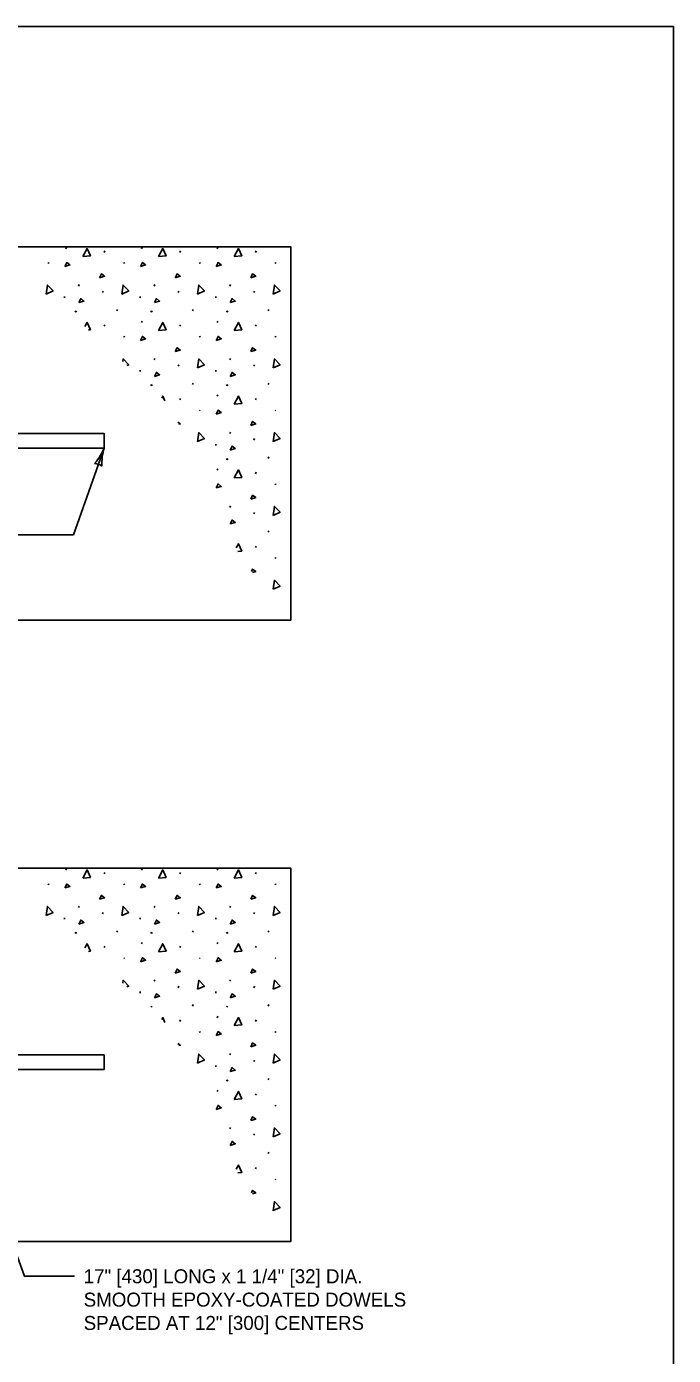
# Model space of a CAD drawing. Extents: x 49991.4 to 50021, y 49987.6 to 50011.4.
# Drawn here: x 50005.84 to 50008.61, y 50005.57 to 50011.26 of the extents above; entities that cross this region are included whole.
import ezdxf

# ---------------------------------------------------------------- set-up
doc = ezdxf.new("R2010")
doc.units = 0
for name, color, linetype in [('Level 1', 7, 'Continuous'), ('Level 2', 7, 'Continuous'), ('Level 3', 7, 'Continuous')]:
    doc.layers.add(name, color=color, linetype=linetype)

msp = doc.modelspace()

# ---------------------------------------------------------------- linework, layer by layer
at = {"layer": 'Level 1'}
for p, q in [((50006.0116, 50010.3112), (50006.0143, 50010.3173)), ((50006.3357, 50010.3112), (50006.3384, 50010.3173)), ((50006.6599, 50010.3112), (50006.6626, 50010.3173)), ((50006.1753, 50010.2956), (50006.1781, 50010.3017)), ((50006.4995, 50010.2956), (50006.5022, 50010.3017)), ((50006.8236, 50010.2956), (50006.8263, 50010.3017)), ((50005.9358, 50010.2523), (50005.9385, 50010.2483)), ((50006.2599, 50010.2523), (50006.2626, 50010.2483)), ((50006.5841, 50010.2523), (50006.5868, 50010.2483)), ((50006.9082, 50010.2523), (50006.9109, 50010.2483)), ((50006.0657, 50010.1515), (50006.0684, 50010.1576)), ((50006.3899, 50010.1515), (50006.3926, 50010.1576)), ((50006.714, 50010.1515), (50006.7167, 50010.1576)), ((50006.0053, 50010.1068), (50006.006, 50010.1007)), ((50006.1686, 50010.1238), (50006.1713, 50010.1299)), ((50006.3295, 50010.1068), (50006.3301, 50010.1007)), ((50006.4927, 50010.1238), (50006.4954, 50010.1299)), ((50006.6536, 50010.1068), (50006.6543, 50010.1007)), ((50006.8169, 50010.1238), (50006.8196, 50010.1299)), ((50006.0515, 50010.0453), (50006.0542, 50010.0412)), ((50006.0542, 50010.0437), (50006.0569, 50010.0397)), ((50006.2302, 50010.0453), (50006.2329, 50010.0514)), ((50006.3756, 50010.0453), (50006.3784, 50010.0412)), ((50006.3784, 50010.0437), (50006.3811, 50010.0397)), ((50006.5543, 50010.0453), (50006.557, 50010.0514)), ((50006.6998, 50010.0453), (50006.7025, 50010.0412)), ((50006.7025, 50010.0437), (50006.7052, 50010.0397)), ((50006.8784, 50010.0453), (50006.8811, 50010.0514)), ((50006.1753, 50009.9796), (50006.1781, 50009.9856)), ((50006.3357, 50009.9951), (50006.3384, 50010.0012)), ((50006.4995, 50009.9796), (50006.5022, 50009.9856)), ((50006.6599, 50009.9951), (50006.6626, 50010.0012)), ((50006.8236, 50009.9796), (50006.8263, 50009.9856)), ((50006.2599, 50009.9362), (50006.2626, 50009.9322)), ((50006.5841, 50009.9362), (50006.5868, 50009.9322)), ((50006.9082, 50009.9362), (50006.9109, 50009.9322)), ((50006.3899, 50009.8354), (50006.3926, 50009.8415)), ((50006.4927, 50009.8077), (50006.4954, 50009.8138)), ((50006.714, 50009.8354), (50006.7167, 50009.8415)), ((50006.8169, 50009.8077), (50006.8196, 50009.8138)), ((50006.3295, 50009.7907), (50006.3301, 50009.7846)), ((50006.6536, 50009.7907), (50006.6543, 50009.7846)), ((50006.3756, 50009.7292), (50006.3784, 50009.7251)), ((50006.3784, 50009.7276), (50006.3811, 50009.7236)), ((50006.5543, 50009.7292), (50006.557, 50009.7353)), ((50006.6998, 50009.7292), (50006.7025, 50009.7251)), ((50006.7025, 50009.7276), (50006.7052, 50009.7236)), ((50006.8784, 50009.7292), (50006.8811, 50009.7353)), ((50006.4995, 50009.6635), (50006.5022, 50009.6696)), ((50006.6599, 50009.679), (50006.6626, 50009.6851)), ((50006.8236, 50009.6635), (50006.8263, 50009.6696)), ((50006.5841, 50009.6202), (50006.5868, 50009.6161)), ((50006.9082, 50009.6202), (50006.9109, 50009.6161)), ((50006.714, 50009.5193), (50006.7167, 50009.5254)), ((50006.6536, 50009.4746), (50006.6543, 50009.4685)), ((50006.8169, 50009.4916), (50006.8196, 50009.4977)), ((50006.6998, 50009.4131), (50006.7025, 50009.409)), ((50006.7025, 50009.4116), (50006.7052, 50009.4075)), ((50006.8784, 50009.4131), (50006.8811, 50009.4192)), ((50006.6599, 50009.3629), (50006.6626, 50009.369)), ((50006.8236, 50009.3474), (50006.8263, 50009.3535)), ((50006.9082, 50009.3041), (50006.9109, 50009.3)), ((50006.714, 50009.2032), (50006.7167, 50009.2093)), ((50006.8169, 50009.1755), (50006.8196, 50009.1816)), ((50006.8784, 50009.097), (50006.8811, 50009.1031)), ((50006.8236, 50009.0313), (50006.8263, 50009.0374)), ((50006.9082, 50008.988), (50006.9109, 50008.9839)), ((50006.0116, 50007.6492), (50006.0143, 50007.6553)), ((50006.3357, 50007.6492), (50006.3384, 50007.6553)), ((50006.6599, 50007.6492), (50006.6626, 50007.6553)), ((50005.9358, 50007.5904), (50005.9385, 50007.5863)), ((50006.1753, 50007.6337), (50006.1781, 50007.6398)), ((50006.2599, 50007.5904), (50006.2626, 50007.5863)), ((50006.4995, 50007.6337), (50006.5022, 50007.6398)), ((50006.5841, 50007.5904), (50006.5868, 50007.5863)), ((50006.8236, 50007.6337), (50006.8263, 50007.6398)), ((50006.9082, 50007.5904), (50006.9109, 50007.5863)), ((50006.0657, 50007.4895), (50006.0684, 50007.4956)), ((50006.3899, 50007.4895), (50006.3926, 50007.4956)), ((50006.714, 50007.4895), (50006.7167, 50007.4956)), ((50006.0053, 50007.4448), (50006.006, 50007.4387)), ((50006.1686, 50007.4618), (50006.1713, 50007.4679)), ((50006.3295, 50007.4448), (50006.3301, 50007.4387)), ((50006.4927, 50007.4618), (50006.4954, 50007.4679)), ((50006.6536, 50007.4448), (50006.6543, 50007.4387)), ((50006.8169, 50007.4618), (50006.8196, 50007.4679)), ((50006.0515, 50007.3833), (50006.0542, 50007.3793)), ((50006.0542, 50007.3818), (50006.0569, 50007.3777)), ((50006.2302, 50007.3833), (50006.2329, 50007.3894)), ((50006.3756, 50007.3833), (50006.3784, 50007.3793)), ((50006.3784, 50007.3818), (50006.3811, 50007.3777)), ((50006.5543, 50007.3833), (50006.557, 50007.3894)), ((50006.6998, 50007.3833), (50006.7025, 50007.3793)), ((50006.7025, 50007.3818), (50006.7052, 50007.3777)), ((50006.8784, 50007.3833), (50006.8811, 50007.3894)), ((50006.1753, 50007.3176), (50006.1781, 50007.3237)), ((50006.3357, 50007.3332), (50006.3384, 50007.3392)), ((50006.4995, 50007.3176), (50006.5022, 50007.3237)), ((50006.6599, 50007.3332), (50006.6626, 50007.3392)), ((50006.8236, 50007.3176), (50006.8263, 50007.3237)), ((50006.2599, 50007.2743), (50006.2626, 50007.2702)), ((50006.5841, 50007.2743), (50006.5868, 50007.2702)), ((50006.9082, 50007.2743), (50006.9109, 50007.2702)), ((50006.3295, 50007.1287), (50006.3301, 50007.1226)), ((50006.3899, 50007.1735), (50006.3926, 50007.1795)), ((50006.4927, 50007.1457), (50006.4954, 50007.1518)), ((50006.6536, 50007.1287), (50006.6543, 50007.1226)), ((50006.714, 50007.1735), (50006.7167, 50007.1795)), ((50006.8169, 50007.1457), (50006.8196, 50007.1518)), ((50006.5543, 50007.0672), (50006.557, 50007.0733)), ((50006.8784, 50007.0672), (50006.8811, 50007.0733)), ((50006.3756, 50007.0672), (50006.3784, 50007.0632)), ((50006.3784, 50007.0657), (50006.3811, 50007.0616)), ((50006.6599, 50007.0171), (50006.6626, 50007.0232)), ((50006.6998, 50007.0672), (50006.7025, 50007.0632)), ((50006.7025, 50007.0657), (50006.7052, 50007.0616)), ((50006.4995, 50007.0015), (50006.5022, 50007.0076)), ((50006.5841, 50006.9582), (50006.5868, 50006.9541)), ((50006.8236, 50007.0015), (50006.8263, 50007.0076)), ((50006.9082, 50006.9582), (50006.9109, 50006.9541)), ((50006.714, 50006.8574), (50006.7167, 50006.8635)), ((50006.6536, 50006.8126), (50006.6543, 50006.8065)), ((50006.8169, 50006.8296), (50006.8196, 50006.8357)), ((50006.6998, 50006.7511), (50006.7025, 50006.7471)), ((50006.7025, 50006.7496), (50006.7052, 50006.7455)), ((50006.8784, 50006.7511), (50006.8811, 50006.7572)), ((50006.6599, 50006.701), (50006.6626, 50006.7071)), ((50006.8236, 50006.6854), (50006.8263, 50006.6915)), ((50006.9082, 50006.6421), (50006.9109, 50006.638)), ((50006.714, 50006.5413), (50006.7167, 50006.5474)), ((50006.8169, 50006.5135), (50006.8196, 50006.5196)), ((50006.8784, 50006.435), (50006.8811, 50006.4411)), ((50006.8236, 50006.3693), (50006.8263, 50006.3754)), ((50006.9082, 50006.326), (50006.9109, 50006.322))]:
    msp.add_line(p, q, dxfattribs=at)
msp.add_lwpolyline([(50008.6146, 50011.2628), (50000.3356, 50011.2628), (50000.3356, 50000.0624), (50008.6146, 50000.0624)], close=True, dxfattribs=at)
for points in [[(50001.9751, 50008.7199), (50006.9751, 50008.7199), (50006.9751, 50010.3199), (50004.5185, 50010.3199)], [(50006.084, 50010.2774), (50006.1023, 50010.3119), (50006.1165, 50010.2801), (50006.0847, 50010.2774)], [(50006.4081, 50010.2774), (50006.4264, 50010.3119), (50006.4406, 50010.2801), (50006.4088, 50010.2774)], [(50006.7323, 50010.2774), (50006.7505, 50010.3119), (50006.7648, 50010.2801), (50006.7329, 50010.2774)], [(50006.0068, 50010.2347), (50006.015, 50010.2517), (50006.0285, 50010.2415), (50006.0068, 50010.2347)], [(50006.1552, 50010.1864), (50006.1633, 50010.2033), (50006.1768, 50010.1931), (50006.1552, 50010.1864)], [(50006.331, 50010.2347), (50006.3391, 50010.2517), (50006.3526, 50010.2415), (50006.331, 50010.2347)], [(50006.4793, 50010.1864), (50006.4874, 50010.2033), (50006.501, 50010.1931), (50006.4793, 50010.1864)], [(50006.6551, 50010.2347), (50006.6632, 50010.2517), (50006.6768, 50010.2415), (50006.6551, 50010.2347)], [(50006.8035, 50010.1864), (50006.8116, 50010.2033), (50006.8251, 50010.1931), (50006.8035, 50010.1864)], [(50005.9268, 50010.1168), (50005.9321, 50010.1554), (50005.9564, 50010.1304), (50005.9274, 50010.117)], [(50006.2509, 50010.1168), (50006.2563, 50010.1554), (50006.2805, 50010.1304), (50006.2515, 50010.117)], [(50006.575, 50010.1168), (50006.5804, 50010.1554), (50006.6046, 50010.1304), (50006.5757, 50010.117)], [(50006.8992, 50010.1168), (50006.9045, 50010.1554), (50006.9288, 50010.1304), (50006.8998, 50010.117)], [(50006.0671, 50010.0805), (50006.0752, 50010.0974), (50006.0887, 50010.0872), (50006.0671, 50010.0805)], [(50006.3912, 50010.0805), (50006.3993, 50010.0974), (50006.4129, 50010.0872), (50006.3912, 50010.0805)], [(50006.7154, 50010.0805), (50006.7235, 50010.0974), (50006.737, 50010.0872), (50006.7154, 50010.0805)], [(50006.0928, 50009.9779), (50006.1023, 50009.9958), (50006.1165, 50009.964), (50006.1084, 50009.9633)], [(50006.4081, 50009.9613), (50006.4264, 50009.9958), (50006.4406, 50009.964), (50006.4088, 50009.9613)], [(50006.7323, 50009.9613), (50006.7505, 50009.9958), (50006.7648, 50009.964), (50006.7329, 50009.9613)], [(50006.331, 50009.9187), (50006.3391, 50009.9356), (50006.3526, 50009.9254), (50006.331, 50009.9187)], [(50006.6551, 50009.9187), (50006.6632, 50009.9356), (50006.6768, 50009.9254), (50006.6551, 50009.9187)], [(50006.4793, 50009.8703), (50006.4874, 50009.8872), (50006.501, 50009.877), (50006.4793, 50009.8703)], [(50006.8035, 50009.8703), (50006.8116, 50009.8872), (50006.8251, 50009.877), (50006.8035, 50009.8703)], [(50006.2546, 50009.8274), (50006.2563, 50009.8394), (50006.2805, 50009.8143), (50006.2726, 50009.8107)], [(50006.575, 50009.8007), (50006.5804, 50009.8394), (50006.6046, 50009.8143), (50006.5757, 50009.8009)], [(50006.8992, 50009.8007), (50006.9045, 50009.8394), (50006.9288, 50009.8143), (50006.8998, 50009.8009)], [(50006.3912, 50009.7644), (50006.3993, 50009.7813), (50006.4129, 50009.7711), (50006.3912, 50009.7644)], [(50006.7154, 50009.7644), (50006.7235, 50009.7813), (50006.737, 50009.7711), (50006.7154, 50009.7644)], [(50006.4221, 50009.6716), (50006.4264, 50009.6797), (50006.4356, 50009.6591)], [(50006.7323, 50009.6452), (50006.7505, 50009.6797), (50006.7648, 50009.6479), (50006.7329, 50009.6452)], [(50006.6551, 50009.6026), (50006.6632, 50009.6195), (50006.6768, 50009.6093), (50006.6551, 50009.6026)], [(50002.7751, 50009.5199), (50006.1751, 50009.5199), (50006.1751, 50009.4574)], [(50006.4913, 50009.5682), (50006.501, 50009.561), (50006.4958, 50009.5593)], [(50006.575, 50009.4846), (50006.5804, 50009.5233), (50006.6046, 50009.4982), (50006.5757, 50009.4848)], [(50006.8035, 50009.5542), (50006.8116, 50009.5711), (50006.8251, 50009.561), (50006.8035, 50009.5542)], [(50006.8992, 50009.4846), (50006.9045, 50009.5233), (50006.9288, 50009.4982), (50006.8998, 50009.4848)], [(50006.7154, 50009.4483), (50006.7235, 50009.4652), (50006.737, 50009.4551), (50006.7154, 50009.4483)], [(50002.7751, 50009.4574), (50006.1751, 50009.4574)], [(50006.7323, 50009.3291), (50006.7505, 50009.3636), (50006.7648, 50009.3318), (50006.7329, 50009.3291)], [(50006.6551, 50009.2865), (50006.6632, 50009.3034), (50006.6768, 50009.2932), (50006.6551, 50009.2865)], [(50006.8035, 50009.2381), (50006.8116, 50009.255), (50006.8251, 50009.2449), (50006.8035, 50009.2381)], [(50006.8992, 50009.1685), (50006.9045, 50009.2072), (50006.9288, 50009.1822), (50006.8998, 50009.1687)], [(50006.7154, 50009.1322), (50006.7235, 50009.1491), (50006.737, 50009.139), (50006.7154, 50009.1322)], [(50006.7413, 50009.0301), (50006.7505, 50009.0475), (50006.7648, 50009.0157), (50006.7478, 50009.0143)], [(50006.8069, 50008.9291), (50006.8116, 50008.9389), (50006.8251, 50008.9288), (50006.8116, 50008.9246)], [(50006.8992, 50008.8524), (50006.9045, 50008.8911), (50006.9288, 50008.8661), (50006.8998, 50008.8526)], [(50001.9751, 50006.058), (50006.9751, 50006.058), (50006.9751, 50007.658), (50004.5185, 50007.658)], [(50006.084, 50007.6154), (50006.1023, 50007.6499), (50006.1165, 50007.6181), (50006.0847, 50007.6154)], [(50006.4081, 50007.6154), (50006.4264, 50007.6499), (50006.4406, 50007.6181), (50006.4088, 50007.6154)], [(50006.7323, 50007.6154), (50006.7505, 50007.6499), (50006.7648, 50007.6181), (50006.7329, 50007.6154)], [(50006.0068, 50007.5728), (50006.015, 50007.5897), (50006.0285, 50007.5795), (50006.0068, 50007.5728)], [(50006.331, 50007.5728), (50006.3391, 50007.5897), (50006.3526, 50007.5795), (50006.331, 50007.5728)], [(50006.6551, 50007.5728), (50006.6632, 50007.5897), (50006.6768, 50007.5795), (50006.6551, 50007.5728)], [(50006.1552, 50007.5244), (50006.1633, 50007.5413), (50006.1768, 50007.5312), (50006.1552, 50007.5244)], [(50006.4793, 50007.5244), (50006.4874, 50007.5413), (50006.501, 50007.5312), (50006.4793, 50007.5244)], [(50006.8035, 50007.5244), (50006.8116, 50007.5413), (50006.8251, 50007.5312), (50006.8035, 50007.5244)], [(50005.9268, 50007.4548), (50005.9321, 50007.4935), (50005.9564, 50007.4685), (50005.9274, 50007.455)], [(50006.2509, 50007.4548), (50006.2563, 50007.4935), (50006.2805, 50007.4685), (50006.2515, 50007.455)], [(50006.575, 50007.4548), (50006.5804, 50007.4935), (50006.6046, 50007.4685), (50006.5757, 50007.455)], [(50006.8992, 50007.4548), (50006.9045, 50007.4935), (50006.9288, 50007.4685), (50006.8998, 50007.455)], [(50006.0671, 50007.4185), (50006.0752, 50007.4354), (50006.0887, 50007.4253), (50006.0671, 50007.4185)], [(50006.3912, 50007.4185), (50006.3993, 50007.4354), (50006.4129, 50007.4253), (50006.3912, 50007.4185)], [(50006.7154, 50007.4185), (50006.7235, 50007.4354), (50006.737, 50007.4253), (50006.7154, 50007.4185)], [(50006.0928, 50007.3159), (50006.1023, 50007.3338), (50006.1165, 50007.302), (50006.1084, 50007.3013)], [(50006.4081, 50007.2993), (50006.4264, 50007.3338), (50006.4406, 50007.302), (50006.4088, 50007.2993)], [(50006.7323, 50007.2993), (50006.7505, 50007.3338), (50006.7648, 50007.302), (50006.7329, 50007.2993)], [(50006.331, 50007.2567), (50006.3391, 50007.2736), (50006.3526, 50007.2635), (50006.331, 50007.2567)], [(50006.6551, 50007.2567), (50006.6632, 50007.2736), (50006.6768, 50007.2635), (50006.6551, 50007.2567)], [(50006.4793, 50007.2083), (50006.4874, 50007.2252), (50006.501, 50007.2151), (50006.4793, 50007.2083)], [(50006.8035, 50007.2083), (50006.8116, 50007.2252), (50006.8251, 50007.2151), (50006.8035, 50007.2083)], [(50006.2546, 50007.1654), (50006.2563, 50007.1774), (50006.2805, 50007.1524), (50006.2726, 50007.1487)], [(50006.575, 50007.1387), (50006.5804, 50007.1774), (50006.6046, 50007.1524), (50006.5757, 50007.1389)], [(50006.8992, 50007.1387), (50006.9045, 50007.1774), (50006.9288, 50007.1524), (50006.8998, 50007.1389)], [(50006.3912, 50007.1024), (50006.3993, 50007.1193), (50006.4129, 50007.1092), (50006.3912, 50007.1024)], [(50006.7154, 50007.1024), (50006.7235, 50007.1193), (50006.737, 50007.1092), (50006.7154, 50007.1024)], [(50006.4221, 50007.0097), (50006.4264, 50007.0177), (50006.4356, 50006.9971)], [(50006.7323, 50006.9832), (50006.7505, 50007.0177), (50006.7648, 50006.9859), (50006.7329, 50006.9832)], [(50006.6551, 50006.9406), (50006.6632, 50006.9575), (50006.6768, 50006.9474), (50006.6551, 50006.9406)], [(50006.4913, 50006.9063), (50006.501, 50006.899), (50006.4958, 50006.8974)], [(50006.8035, 50006.8922), (50006.8116, 50006.9091), (50006.8251, 50006.899), (50006.8035, 50006.8922)], [(50002.7751, 50006.858), (50006.1751, 50006.858), (50006.1751, 50006.7955)], [(50006.575, 50006.8226), (50006.5804, 50006.8613), (50006.6046, 50006.8363), (50006.5757, 50006.8229)], [(50006.8992, 50006.8226), (50006.9045, 50006.8613), (50006.9288, 50006.8363), (50006.8998, 50006.8229)], [(50002.7751, 50006.7955), (50006.1751, 50006.7955)], [(50006.7154, 50006.7863), (50006.7235, 50006.8032), (50006.737, 50006.7931), (50006.7154, 50006.7863)], [(50006.7323, 50006.6671), (50006.7505, 50006.7017), (50006.7648, 50006.6699), (50006.7329, 50006.6671)], [(50006.6551, 50006.6245), (50006.6632, 50006.6414), (50006.6768, 50006.6313), (50006.6551, 50006.6245)], [(50006.8035, 50006.5761), (50006.8116, 50006.5931), (50006.8251, 50006.5829), (50006.8035, 50006.5761)], [(50006.8992, 50006.5065), (50006.9045, 50006.5452), (50006.9288, 50006.5202), (50006.8998, 50006.5068)], [(50006.7154, 50006.4702), (50006.7235, 50006.4872), (50006.737, 50006.477), (50006.7154, 50006.4702)], [(50006.7413, 50006.3681), (50006.7505, 50006.3856), (50006.7648, 50006.3538), (50006.7478, 50006.3523)], [(50006.8069, 50006.2671), (50006.8116, 50006.277), (50006.8251, 50006.2668), (50006.8116, 50006.2626)], [(50006.8992, 50006.1905), (50006.9045, 50006.2291), (50006.9288, 50006.2041), (50006.8998, 50006.1907)]]:
    msp.add_lwpolyline(points, dxfattribs=at)
at = {"layer": 'Level 3'}
for p, q in [((50006.0445, 50009.0854), (50006.1751, 50009.4574)), ((50004.8675, 50009.0854), (50006.0445, 50009.0854))]:
    msp.add_line(p, q, dxfattribs=at)
msp.add_lwpolyline([(50006.0475, 50005.9095), (50005.8339, 50005.9095), (50005.5097, 50006.7955)], dxfattribs=at)
for centre, radius, start, end in [((50005.9685, 50009.5397), 0.2223, 318.1089, 338.2924), ((50005.9685, 50009.5397), 0.2223, 318.1089, 338.2924), ((50006.3985, 50009.3912), 0.233, 163.4802, 182.7301), ((50006.3985, 50009.3912), 0.233, 163.4802, 182.7301), ((50006.1326, 50009.3365), 0.0548, 52.7917, 88.5141), ((50006.1326, 50009.3365), 0.0548, 52.7917, 88.5141)]:
    msp.add_arc(centre, radius, start, end, dxfattribs=at)

# ---------------------------------------------------------------- texts
at = {"layer": 'Level 2'}
for s, p in [('17" [430] LONG x 1 1/4" [32] DIA. ', (50006.0875, 50005.8795)), ('SMOOTH EPOXY-COATED DOWELS', (50006.0875, 50005.7795)), ('SPACED AT 12" [300] CENTERS', (50006.0875, 50005.6795))]:
    msp.add_text(s, height=0.06, dxfattribs=at).set_placement(p)

doc.saveas('drawing.dxf')
